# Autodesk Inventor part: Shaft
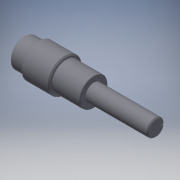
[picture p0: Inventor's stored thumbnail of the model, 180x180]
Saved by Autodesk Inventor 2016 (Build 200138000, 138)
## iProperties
Created: 2015-03
Part Number: Shaft
Material: Steel
Document SubType Name: Modeling
Designer: Uglješa
Density: 7.85 g/cm^3
Appearance: Steel
Mass: 353.264 g
Surface Area: 91.0686 cm^2
Volume: 45.0018 cm^3
CustomPartVersion: 1
Author: Uglješa
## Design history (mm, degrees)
sketch "Main Sketch"
  geometry: L1 (0, 0)-(117, 0) reference; L2 (0, 0)-(0, 12.5); L3 (0, 12.5)-(12, 12.5); L4 (12, 12.5)-(12, 15); L5 (37, 15)-(37, 12.5); L6 (12, 15)-(37, 15); L7 (37, 12.5)-(62, 12.5); L8 (117, 7.5)-(117, 0); L9 (62, 7.5)-(117, 7.5); L10 (62, 12.5)-(62, 7.5)
  constraints: 20 end point, 5 vertical, 2 horizontal
  dimensions: "d3" = 25 diameter of L3 L1 (derived); "d4" = 30 diameter of L6 L1 (derived); "d5" = 25 diameter of L7 L1 (derived); "d6" = 15 diameter of L9 L1 (derived)
revolve "Revolution1" sketch "Main Sketch" stored, may be unused: angle "d7" = 0 deg
chamfer "Chamfer13" distance "d54" = 1; stored, may be unused: second distance "d55" = 0.125, angle "d56" = 45 deg
chamfer "Chamfer12" distance "d51" = 1; stored, may be unused: second distance "d52" = 0.125, angle "d53" = 45 deg
fillet "Fillet9" dims "d47" = 1
node "Keyway4"
fillet "Fillet1" dims "d11" = 1
chamfer "Chamfer3" distance "d15" = 1; stored, may be unused: second distance "d16" = 0.125, angle "d17" = 45 deg
fillet "Fillet3" dims "d19" = 1
chamfer "Chamfer4" distance "d21" = 1; stored, may be unused: second distance "d22" = 0.125, angle "d23" = 45 deg
sketch "Sketch3"
  geometry: L1 (0, 0)-(0, 8.131); L2 (-0.5, 7.917)-(0.5, 7.917); L3 (0.5, 7.917)-(0.5, 4); L4 (0.5, 4)-(-0.5, 4); L5 (-0.5, 4)-(-0.5, 7.917)
  constraints: 10 end point, 2 parallel, 1 horizontal, 1 perpendicular, 1 vertical
  dimensions: "d57" = 1 distance between parallel lines of L3 L5; "d58" = 1 diameter of L5 L1; "d59" = 4 distance from line of L1.start L4
extrude "Extrusion1" cut sketch "Sketch3" distance "d60" = 0.5; taper "d61" = 0 deg
body "Solid1"
feature "iFeature3:4"
other parameters: "d0" = 0, "d1" = 0, "d2" = 0
